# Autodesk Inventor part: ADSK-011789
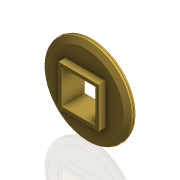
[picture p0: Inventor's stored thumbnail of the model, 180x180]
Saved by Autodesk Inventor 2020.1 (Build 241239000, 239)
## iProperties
Created: 1999-08
Part Number: ADSK-011789
Document SubType Name: Modeling
Designer: Autodesk
Material: Générique
Density: 1 g/cm^3
Appearance: Vorgabe
Mass: 63.2686 g
Surface Area: 204.174 cm^2
Volume: 63.2686 cm^3
Control State: 0
Master: False
Checked Out: False
Shininess: 0.0
Length Units: 11269
Angle Units: 11279
Time Units: 11290
Mass Units: 11283
Length Display Precision: 3
Angle Display Precision: 2
Compacted: True
Dimensions: 98,2x25,6x98,2 mm
Mass: 0,063 kg
VLT_Material: Generic
DocNumber: ADSK-011789.ipt
Folder: 01 - Themengebiete\Simplification\01 - Packaging machine\
VDS_Category: 3D Komponenten
Density: 0.0
Volumn: 0.0
Area: 0.0
PropertySet Name: Model Information
Author: Autodesk
Revision Number: -
Title: wheel
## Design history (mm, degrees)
node "Extrusion1" dims "d1" = 10, "d2" = 0
  sketch "Sketch1"
    geometry: C1 r 48.5 at (0, 0)
    constraints: 1 centre point
    dimensions: "d0" = 97 diameter of C1
node "Chamfer1" dims "d17" = 3, "d18" = 6, "d25" = 45 deg
node "Chamfer2" dims "d19" = 3, "d20" = 6, "d26" = 45 deg
node "Extrusion2" dims "d5" = 7.8, "d6" = 0
  sketch "Sketch2"
    geometry: L1 (-22.5, 22.5)-(22.5, 22.5); L2 (22.5, 22.5)-(22.5, -22.5); L3 (22.5, -22.5)-(-22.5, -22.5); L4 (-22.5, -22.5)-(-22.5, 22.5); L5 (-22.5, 0)-(22.5, 0) reference; L6 (0, 22.5)-(0, -22.5) reference
    constraints: 12 end point, 4 midpoint, 2 horizontal, 2 parallel, 1 perpendicular, 1 vertical
    dimensions: "d3" = 22.5 distance between parallel lines of L1 L5; "d4" = 22.5 distance between parallel lines of L4 L6 (= d3)
node "Mirror1"
node "Extrusion3" dims "d9" = 7.9375, "d10" = 0
  sketch "Sketch3"
    geometry: L1 (-19, 19)-(19, 19); L2 (19, 19)-(19, -19); L3 (19, -19)-(-19, -19); L4 (-19, -19)-(-19, 19); L5 (-19, 0)-(19, 0) reference; L6 (0, 19)-(0, -19) reference
    constraints: 12 end point, 4 midpoint, 2 horizontal, 2 parallel, 1 perpendicular, 1 vertical
    dimensions: "d7" = 38 distance of L3.end L1.start; "d8" = 38 distance of L2.end L3.end (= d7)
node "Extrusion4" dims "d23" = 0.254, "d24" = 0
  sketch "Sketch9"
    geometry: C1 r 48.5 at (0, 0) reference; C2 r 49.075 at (0, 0); C3 r 49 at (0, 0)
    constraints: 2 centre point, 1 coincident
    dimensions: "d21" = 98.15 diameter of C2; "d22" = 98 diameter of C3
workplane "Work Plane1"
node "Solide1"
node "Corps solides"
node "Corps surfaciques"
